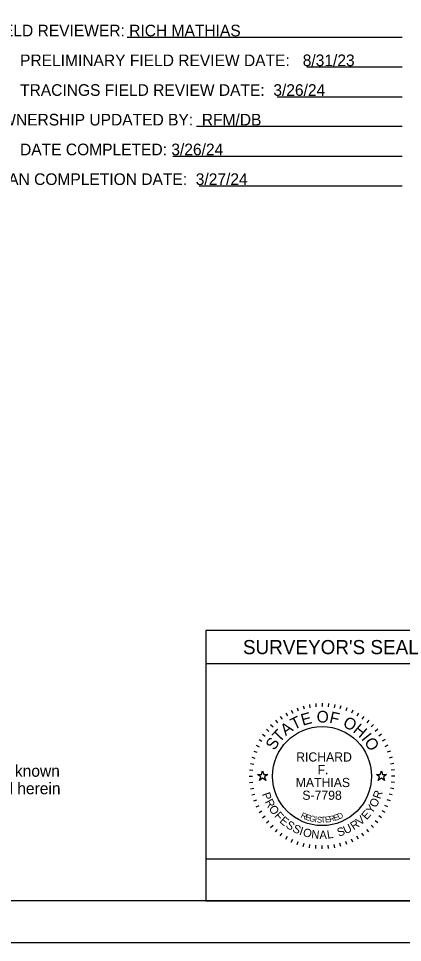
# Model space of a CAD drawing. Extents: x -8.8 to 41.4, y 0 to 34.6.
# Drawn here: x 26.95 to 31.57, y 0 to 11.1 of the extents above; entities that cross this region are included whole.
import ezdxf

# ---------------------------------------------------------------- set-up
doc = ezdxf.new("R2010")
doc.units = 0
for name, color, linetype in [('Default', 7, 'Continuous'), ('SH_Border', 7, 'Continuous'), ('SH_Cut_Line', 7, 'Continuous'), ('SH_Data', 7, 'Continuous'), ('SH_Text', 7, 'Continuous')]:
    doc.layers.add(name, color=color, linetype=linetype)

msp = doc.modelspace()

# ---------------------------------------------------------------- linework, layer by layer
at = {"layer": 'Default'}
for points in [[(29.824, 2.02), (29.871, 2.02), (29.885, 2.065), (29.899, 2.02), (29.946, 2.02), (29.908, 1.992), (29.923, 1.948), (29.885, 1.975), (29.847, 1.948), (29.862, 1.992)], [(31.254, 2.02), (31.301, 2.02), (31.315, 2.065), (31.329, 2.02), (31.376, 2.02), (31.338, 1.992), (31.353, 1.948), (31.315, 1.975), (31.277, 1.948), (31.292, 1.992)]]:
    msp.add_lwpolyline(points, close=True, dxfattribs=at)
at = {"layer": 'SH_Border'}
for p, q in [((32, 3.75), (29.2, 3.75)), ((29.2, 3.75), (29.2, 0.5)), ((32, 3.35), (29.2, 3.35)), ((30.23, 2.793), (30.247, 2.757)), ((30.301, 2.822), (30.314, 2.785)), ((30.374, 2.845), (30.384, 2.807)), ((30.448, 2.862), (30.455, 2.822)), ((30.524, 2.872), (30.527, 2.832)), ((30.6, 2.875), (30.6, 2.835)), ((30.676, 2.872), (30.673, 2.832)), ((30.752, 2.862), (30.745, 2.822)), ((30.826, 2.845), (30.816, 2.807)), ((30.899, 2.822), (30.886, 2.785)), ((30.97, 2.793), (30.953, 2.757)), ((30.038, 2.67), (30.063, 2.64)), ((30.098, 2.717), (30.121, 2.684)), ((30.163, 2.758), (30.183, 2.723)), ((31.037, 2.758), (31.017, 2.723)), ((31.102, 2.717), (31.079, 2.684)), ((31.162, 2.67), (31.137, 2.64)), ((29.93, 2.562), (29.96, 2.537)), ((29.981, 2.619), (30.01, 2.59)), ((31.219, 2.619), (31.19, 2.59)), ((31.27, 2.562), (31.24, 2.537)), ((29.883, 2.502), (29.916, 2.479)), ((31.317, 2.502), (31.284, 2.479)), ((29.807, 2.37), (29.843, 2.353)), ((29.842, 2.438), (29.877, 2.418)), ((31.358, 2.438), (31.323, 2.418)), ((31.393, 2.37), (31.357, 2.353)), ((29.755, 2.226), (29.793, 2.216)), ((29.778, 2.299), (29.815, 2.286)), ((31.422, 2.299), (31.385, 2.286)), ((31.445, 2.226), (31.407, 2.216)), ((29.738, 2.152), (29.778, 2.145)), ((31.462, 2.152), (31.422, 2.145)), ((29.725, 2), (29.765, 2)), ((29.728, 2.076), (29.768, 2.073)), ((31.472, 2.076), (31.432, 2.073)), ((31.475, 2), (31.435, 2)), ((29.728, 1.924), (29.768, 1.927)), ((31.472, 1.924), (31.432, 1.927)), ((29.738, 1.848), (29.778, 1.855)), ((29.755, 1.774), (29.793, 1.784)), ((31.445, 1.774), (31.407, 1.784)), ((31.462, 1.848), (31.422, 1.855)), ((29.778, 1.701), (29.815, 1.714)), ((31.422, 1.701), (31.385, 1.714)), ((29.807, 1.63), (29.843, 1.647)), ((29.842, 1.563), (29.877, 1.583)), ((31.358, 1.563), (31.323, 1.583)), ((31.393, 1.63), (31.357, 1.647)), ((29.883, 1.498), (29.916, 1.521)), ((29.93, 1.438), (29.96, 1.463)), ((31.27, 1.438), (31.24, 1.463)), ((31.317, 1.498), (31.284, 1.521)), ((29.981, 1.381), (30.01, 1.41)), ((30.038, 1.33), (30.063, 1.36)), ((31.162, 1.33), (31.137, 1.36)), ((31.219, 1.381), (31.19, 1.41)), ((30.098, 1.283), (30.121, 1.316)), ((30.163, 1.242), (30.183, 1.277)), ((30.23, 1.207), (30.247, 1.243)), ((30.97, 1.207), (30.953, 1.243)), ((31.037, 1.242), (31.017, 1.277)), ((31.102, 1.283), (31.079, 1.316)), ((30.301, 1.178), (30.314, 1.215)), ((30.374, 1.155), (30.384, 1.193)), ((30.448, 1.138), (30.455, 1.178)), ((30.524, 1.128), (30.527, 1.168)), ((30.6, 1.125), (30.6, 1.165)), ((30.676, 1.128), (30.673, 1.168)), ((30.752, 1.138), (30.745, 1.178)), ((30.826, 1.155), (30.816, 1.193)), ((30.899, 1.178), (30.886, 1.215)), ((32, 0.5), (29.2, 0.5))]:
    msp.add_line(p, q, dxfattribs=at)
msp.add_lwpolyline([(32, 0.5), (32, 1), (29.2, 1), (29.2, 0.5)], close=True, dxfattribs=at)
msp.add_circle((30.6, 2), 0.595, dxfattribs=at)
at = {"layer": 'SH_Cut_Line'}
msp.add_lwpolyline([(1.5, 21.5), (33.5, 21.5), (33.5, 0.5), (1.5, 0.5)], close=True, dxfattribs=at)
at = {"layer": 'SH_Data'}
for p, q in [((28.255, 10.879), (31.563, 10.879)), ((30.418, 10.521), (31.563, 10.521)), ((30.06, 10.164), (31.563, 10.164)), ((29.091, 9.808), (31.563, 9.808)), ((28.805, 9.45), (31.563, 9.45)), ((29.12, 9.093), (31.563, 9.093))]:
    msp.add_line(p, q, dxfattribs=at)
at = {"layer": 'SH_Text'}
msp.add_lwpolyline([(0, 0), (34, 0), (34, 22), (0, 22)], close=True, dxfattribs=at)

# ---------------------------------------------------------------- texts
at = {"layer": 'SH_Border'}
for s, height, p in [("SURVEYOR'S SEAL", 0.17, (29.648, 3.465)), ('RICHARD', 0.11, (30.289, 2.175)), ('F.', 0.11, (30.546, 2.022)), ('MATHIAS', 0.11, (30.283, 1.868)), ('S-7798', 0.11, (30.363, 1.715))]:
    msp.add_text(s, height=height, dxfattribs=at).set_placement(p)
for s, height, rotation, p in [('O', 0.14, 359.7812, (30.535, 2.644)), ('T', 0.14, 25.7167, (30.262, 2.552)), ('E', 0.14, 15.7571, (30.368, 2.604)), ('F', 0.14, 347.4362, (30.681, 2.642)), ('O', 0.14, 332.2586, (30.84, 2.602)), ('T', 0.14, 46.4344, (30.088, 2.396)), ('A', 0.14, 36.4747, (30.163, 2.478)), ('H', 0.14, 319.9136, (30.963, 2.536)), ('S', 0.14, 57.1924, (30.028, 2.301)), ('I', 0.14, 308.367, (31.066, 2.448)), ('O', 0.14, 303.1491, (31.102, 2.409)), ('P', 0.1, 289.7431, (29.875, 1.784)), ('R', 0.1, 70.983, (31.301, 1.717)), ('R', 0.1, 296.9802, (29.909, 1.693)), ('Y', 0.1, 55.5058, (31.2, 1.54)), ('O', 0.1, 62.7428, (31.25, 1.613)), ('O', 0.1, 304.7158, (29.953, 1.608)), ('F', 0.1, 312.956, (30.019, 1.516)), ('R', 0.07, 334.487, (30.337, 1.505)), ('D', 0.07, 23.3052, (30.801, 1.477)), ('E', 0.1, 48.2687, (31.137, 1.467)), ('E', 0.1, 319.6885, (30.081, 1.45)), ('S', 0.1, 326.9255, (30.155, 1.389)), ('E', 0.07, 341.04, (30.391, 1.48)), ('G', 0.07, 347.4752, (30.441, 1.462)), ('I', 0.07, 353.7858, (30.509, 1.447)), ('S', 0.07, 356.8926, (30.536, 1.443)), ('T', 0.07, 3.0061, (30.586, 1.439)), ('E', 0.07, 6.0117, (30.639, 1.441)), ('R', 0.07, 11.9184, (30.692, 1.447)), ('E', 0.07, 17.6836, (30.75, 1.46)), ('R', 0.1, 33.296, (30.981, 1.347)), ('V', 0.1, 41.0316, (31.061, 1.401)), ('S', 0.1, 334.1626, (30.236, 1.337)), ('I', 0.1, 341.3997, (30.319, 1.298)), ('O', 0.1, 345.1351, (30.362, 1.282)), ('N', 0.1, 353.3752, (30.466, 1.255)), ('A', 0.1, 1.1108, (30.569, 1.244)), ('L', 0.1, 8.3479, (30.666, 1.247)), ('S', 0.1, 18.3234, (30.8, 1.271)), ('U', 0.1, 25.5604, (30.883, 1.299))]:
    msp.add_text(s, height=height, rotation=rotation, dxfattribs=at).set_placement(p)
at = {"layer": 'SH_Data'}
for s, p in [('FIELD REVIEWER: RICH MATHIAS', (26.594, 10.889)), ('PRELIMINARY FIELD REVIEW DATE:   8/31/23', (26.966, 10.531)), ('TRACINGS FIELD REVIEW DATE:  3/26/24', (26.966, 10.174)), ('OWNERSHIP UPDATED BY:  RFM/DB', (26.594, 9.818)), ('DATE COMPLETED: 3/26/24', (26.966, 9.46)), ('PLAN COMPLETION DATE:  3/27/24', (26.594, 9.103)), ('All of my work contained herein was conducted in accordance with Ohio Administrative Code 4733-37 commonly known', (17.528, 1.992)), ('as "A Minimum Standards for Boundary Surveys in the State of Ohio" unless noted.  The words I and my as used herein', (17.528, 1.782))]:
    msp.add_text(s, height=0.14, dxfattribs=at).set_placement(p)

doc.saveas('drawing.dxf')
